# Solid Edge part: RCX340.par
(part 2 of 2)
sketch for "ExtrudedCutout_67" plane through (0, 0, 0) normal (0, 0, 1) x-axis (1, 0, 0)
  line (-7.15, 79.15) -> (-7.15, 26.85)
  line (-7.15, 26.85) -> (24.15, 26.85)
  line (24.15, 26.85) -> (24.15, 31.85)
  line (24.15, 31.85) -> (53.85, 31.85)
  line (53.85, 31.85) -> (53.85, 26.85)
  line (53.85, 26.85) -> (85.15, 26.85)
  line (85.15, 26.85) -> (85.15, 32.15)
  line (85.15, 32.15) -> (-6.85, 32.15)
  line (-6.85, 32.15) -> (-6.85, 78.85)
  line (-6.85, 78.85) -> (4.15, 78.85)
  line (4.15, 78.85) -> (4.15, 79.15)
  line (4.15, 79.15) -> (-7.15, 79.15)
extrude "ExtrudedCutout_67" cut finite 0.1 along -normal
sketch for "unnamed RevolvedProtrusion 3" plane through (-168, 0, 0) normal (1, 0, 0) x-axis (0, 1, 0)
  line (14.5, -6.5) -> (10.5, -6.5)
  line (10.5, -6.5) -> (10.5, -6)
  line (10.5, -6) -> (11, -6)
  line (11, -6) -> (11, -3.9)
  arc centre (12.5, -3.9) radius 1.5 from (11, -3.9) to (12.5, -2.4) cw
  line (12.5, -2.4) -> (14.5, -2.4)
  line (14.5, -2.4) -> (14.5, -6.5)
revolve "unnamed RevolvedProtrusion 3" add finite 360 deg about sketch line (14.5, -2.4) -> (14.5, -6.5)
sketch for "ExtrudedCutout_68" plane through (0, 0, 0) normal (0, 0, 1) x-axis (1, 0, 0)
  line (-170.1, 14.9) -> (-170.1, 14.1)
  line (-170.1, 14.1) -> (-168.9, 14.1)
  arc centre (-168.9, 13.6) radius 0.5 from (-168.9, 14.1) to (-168.4, 13.6) cw
  line (-168.4, 13.6) -> (-168.4, 12.4)
  line (-168.4, 12.4) -> (-167.6, 12.4)
  line (-167.6, 12.4) -> (-167.6, 13.6)
  arc centre (-167.1, 13.6) radius 0.5 from (-167.6, 13.6) to (-167.1, 14.1) cw
  line (-167.1, 14.1) -> (-165.9, 14.1)
  line (-165.9, 14.1) -> (-165.9, 14.9)
  line (-165.9, 14.9) -> (-167.1, 14.9)
  arc centre (-167.1, 15.4) radius 0.5 from (-167.1, 14.9) to (-167.6, 15.4) cw
  line (-167.6, 15.4) -> (-167.6, 16.6)
  line (-167.6, 16.6) -> (-168.4, 16.6)
  line (-168.4, 16.6) -> (-168.4, 15.4)
  arc centre (-168.9, 15.4) radius 0.5 from (-168.4, 15.4) to (-168.9, 14.9) cw
  line (-168.9, 14.9) -> (-170.1, 14.9)
extrude "ExtrudedCutout_68" cut finite 3.777 along -normal
sketch for "ExtrudedProtrusion_51" #1 plane through (0, 0, -15) normal (0, 0, 1) x-axis (1, 0, 0)
  line (-165.9, 70.83) -> (-165.9, 39.77)
  line (-165.9, 39.77) -> (-157.5, 39.77)
  line (-157.5, 39.77) -> (-157.5, 70.83)
  line (-157.5, 70.83) -> (-165.9, 70.83)
sketch for "ExtrudedProtrusion_51" #2 plane through (0, 0, -15) normal (0, 0, 1) x-axis (1, 0, 0)
  line (-164.2, 69.83) -> (-164.2, 40.67)
  line (-164.2, 40.67) -> (-161.8, 40.67)
  line (-161.8, 40.67) -> (-161.8, 41.47)
  line (-161.8, 41.47) -> (-160.8, 41.47)
  line (-160.8, 41.47) -> (-160.8, 40.67)
  line (-160.8, 40.67) -> (-159.1, 40.67)
  line (-159.1, 40.67) -> (-159.1, 41.47)
  line (-159.1, 41.47) -> (-158.7, 41.47)
  line (-158.7, 41.47) -> (-158.7, 42.2733)
  arc centre (-161.3, 43.77) radius 3 from (-158.7, 42.2733) to (-158.7, 45.2667) ccw
  line (-158.7, 45.2667) -> (-158.7, 45.97)
  line (-158.7, 45.97) -> (-159.1, 45.97)
  line (-159.1, 45.97) -> (-159.1, 46.57)
  line (-159.1, 46.57) -> (-158.7, 46.57)
  line (-158.7, 46.57) -> (-158.7, 49.8933)
  arc centre (-161.3, 51.39) radius 3 from (-158.7, 49.8933) to (-158.7, 52.8867) ccw
  line (-158.7, 52.8867) -> (-158.7, 53.59)
  line (-158.7, 53.59) -> (-159.1, 53.59)
  line (-159.1, 53.59) -> (-159.1, 54.19)
  line (-159.1, 54.19) -> (-158.7, 54.19)
  line (-158.7, 54.19) -> (-158.7, 57.5133)
  arc centre (-161.3, 59.01) radius 3 from (-158.7, 57.5133) to (-158.7, 60.5067) ccw
  line (-158.7, 60.5067) -> (-158.7, 61.21)
  line (-158.7, 61.21) -> (-159.1, 61.21)
  line (-159.1, 61.21) -> (-159.1, 61.81)
  line (-159.1, 61.81) -> (-158.7, 61.81)
  line (-158.7, 61.81) -> (-158.7, 65.1333)
  arc centre (-161.3, 66.63) radius 3 from (-158.7, 65.1333) to (-158.7, 68.1267) ccw
  line (-158.7, 68.1267) -> (-158.7, 68.83)
  line (-158.7, 68.83) -> (-159.1, 68.83)
  line (-159.1, 68.83) -> (-159.1, 69.83)
  line (-159.1, 69.83) -> (-164.2, 69.83)
extrude "ExtrudedProtrusion_51" add finite 15 along +normal
sketch for "ExtrudedProtrusion_52" plane through (0, 0, -15) normal (0, 0, 1) x-axis (1, 0, 0)
  line (-161.8, 67.33) -> (-161.8, 66.33)
  line (-161.8, 66.33) -> (-160.8, 66.33)
  line (-160.8, 66.33) -> (-160.8, 67.33)
  line (-160.8, 67.33) -> (-161.8, 67.33)
extrude "ExtrudedProtrusion_52" add finite 10 along +normal
pattern "unnamed Pattern 10" of "ExtrudedProtrusion_52"
extrude "unnamed Protrusion 16" add finite 10
extrude "unnamed Protrusion 17" add finite 10
extrude "unnamed Protrusion 18" add finite 10
sketch for "ExtrudedCutout_69" #1 plane through (0, 0, 0) normal (0, 0, 1) x-axis (1, 0, 0)
  circle centre (114.4, 116.5) radius 2.5
sketch for "ExtrudedCutout_69" #2 plane through (0, 0, 0) normal (0, 0, 1) x-axis (1, 0, 0)
  circle centre (114.4, 116.5) radius 1.75
extrude "ExtrudedCutout_69" cut finite 5 along -normal
"ExtrudedProtrusion_56" has 41 sketches; the first 24 follow
sketch for "ExtrudedProtrusion_56" #1 plane through (-177.5, 0, 0) normal (1, 0, 0) x-axis (0, 1, 0)
  arc centre (107.75, -43.75) radius 3 from (107.75, -40.75) to (104.75, -43.75) ccw
  line (104.75, -43.75) -> (104.75, -123.25)
  arc centre (107.75, -123.25) radius 3 from (104.75, -123.25) to (107.75, -126.25) ccw
  line (107.75, -126.25) -> (187.25, -126.25)
  arc centre (187.25, -123.25) radius 3 from (187.25, -126.25) to (190.25, -123.25) ccw
  line (190.25, -123.25) -> (190.25, -43.75)
  arc centre (187.25, -43.75) radius 3 from (190.25, -43.75) to (187.25, -40.75) ccw
  line (187.25, -40.75) -> (107.75, -40.75)
sketch for "ExtrudedProtrusion_56" #2 plane through (-177.5, 0, 0) normal (1, 0, 0) x-axis (0, 1, 0)
  circle centre (183.25, -119.25) radius 5
sketch for "ExtrudedProtrusion_56" #3 plane through (-177.5, 0, 0) normal (1, 0, 0) x-axis (0, 1, 0)
  circle centre (111.75, -119.25) radius 5
sketch for "ExtrudedProtrusion_56" #4 plane through (-177.5, 0, 0) normal (1, 0, 0) x-axis (0, 1, 0)
  line (121.1695, -111.2447) -> (116.9256, -115.4886)
  arc centre (147.5, -83.5) radius 44.25 from (116.9256, -115.4886) to (123.2294, -120.5) ccw
  line (123.2294, -120.5) -> (131.8615, -120.5)
  arc centre (131.8615, -119.5) radius 1 from (131.8615, -120.5) to (132.2599, -118.5828) ccw
  arc centre (147.5, -83.5) radius 38.25 from (132.2599, -118.5828) to (121.1695, -111.2447) cw
sketch for "ExtrudedProtrusion_56" #5 plane through (-177.5, 0, 0) normal (1, 0, 0) x-axis (0, 1, 0)
  arc centre (147.5, -83.5) radius 38.25 from (173.8305, -111.2447) to (162.7401, -118.5828) cw
  arc centre (163.1385, -119.5) radius 1 from (162.7401, -118.5828) to (163.1385, -120.5) ccw
  line (163.1385, -120.5) -> (171.7706, -120.5)
  arc centre (147.5, -83.5) radius 44.25 from (171.7706, -120.5) to (178.0744, -115.4886) ccw
  line (178.0744, -115.4886) -> (173.8305, -111.2447)
sketch for "ExtrudedProtrusion_56" #6 plane through (-177.5, 0, 0) normal (1, 0, 0) x-axis (0, 1, 0)
  line (126.8288, -105.5854) -> (122.5842, -109.83)
  arc centre (147.5, -83.5) radius 36.25 from (122.5842, -109.83) to (146.5, -119.7362) ccw
  line (146.5, -119.7362) -> (146.5, -113.7335)
  arc centre (147.5, -83.5) radius 30.25 from (146.5, -113.7335) to (126.8288, -105.5854) cw
sketch for "ExtrudedProtrusion_56" #7 plane through (-177.5, 0, 0) normal (1, 0, 0) x-axis (0, 1, 0)
  arc centre (147.5, -83.5) radius 30.25 from (168.1712, -105.5854) to (148.5, -113.7335) cw
  line (148.5, -113.7335) -> (148.5, -119.7362)
  arc centre (147.5, -83.5) radius 36.25 from (148.5, -119.7362) to (172.4158, -109.83) ccw
  line (172.4158, -109.83) -> (168.1712, -105.5854)
sketch for "ExtrudedProtrusion_56" #8 plane through (-177.5, 0, 0) normal (1, 0, 0) x-axis (0, 1, 0)
  line (108.75, -105) -> (106.5, -105)
  line (106.5, -105) -> (106.5, -110)
  line (106.5, -110) -> (108.75, -110)
  line (108.75, -110) -> (108.75, -105)
sketch for "ExtrudedProtrusion_56" #9 plane through (-177.5, 0, 0) normal (1, 0, 0) x-axis (0, 1, 0)
  line (186.25, -105) -> (186.25, -110)
  line (186.25, -110) -> (188.5, -110)
  line (188.5, -110) -> (188.5, -105)
  line (188.5, -105) -> (186.25, -105)
sketch for "ExtrudedProtrusion_56" #10 plane through (-177.5, 0, 0) normal (1, 0, 0) x-axis (0, 1, 0)
  line (132.4899, -99.9243) -> (128.2439, -104.1704)
  arc centre (147.5, -83.5) radius 28.25 from (128.2439, -104.1704) to (146.5, -111.7323) ccw
  line (146.5, -111.7323) -> (146.5, -105.7275)
  arc centre (147.5, -83.5) radius 22.25 from (146.5, -105.7275) to (132.4899, -99.9243) cw
sketch for "ExtrudedProtrusion_56" #11 plane through (-177.5, 0, 0) normal (1, 0, 0) x-axis (0, 1, 0)
  arc centre (147.5, -83.5) radius 22.25 from (162.5101, -99.9243) to (148.5, -105.7275) cw
  line (148.5, -105.7275) -> (148.5, -111.7323)
  arc centre (147.5, -83.5) radius 28.25 from (148.5, -111.7323) to (166.7561, -104.1704) ccw
  line (166.7561, -104.1704) -> (162.5101, -99.9243)
sketch for "ExtrudedProtrusion_56" #12 plane through (-177.5, 0, 0) normal (1, 0, 0) x-axis (0, 1, 0)
  arc centre (111.5, -99.1385) radius 1 from (112.4172, -98.7401) to (110.5, -99.1385) ccw
  line (110.5, -99.1385) -> (110.5, -107.7706)
  arc centre (147.5, -83.5) radius 44.25 from (110.5, -107.7706) to (115.5114, -114.0744) ccw
  line (115.5114, -114.0744) -> (119.7553, -109.8305)
  arc centre (147.5, -83.5) radius 38.25 from (119.7553, -109.8305) to (112.4172, -98.7401) cw
sketch for "ExtrudedProtrusion_56" #13 plane through (-177.5, 0, 0) normal (1, 0, 0) x-axis (0, 1, 0)
  arc centre (183.5, -99.1385) radius 1 from (184.5, -99.1385) to (182.5828, -98.7401) ccw
  arc centre (147.5, -83.5) radius 38.25 from (182.5828, -98.7401) to (175.2447, -109.8305) cw
  line (175.2447, -109.8305) -> (179.4886, -114.0744)
  arc centre (147.5, -83.5) radius 44.25 from (179.4886, -114.0744) to (184.5, -107.7706) ccw
  line (184.5, -107.7706) -> (184.5, -99.1385)
sketch for "ExtrudedProtrusion_56" #14 plane through (-177.5, 0, 0) normal (1, 0, 0) x-axis (0, 1, 0)
  line (135.4988, -96.9154) -> (133.9057, -98.5085)
  arc centre (147.5, -83.5) radius 20.25 from (133.9057, -98.5085) to (146.5, -103.7253) ccw
  line (146.5, -103.7253) -> (146.5, -101.4722)
  arc centre (147.5, -83.5) radius 18 from (146.5, -101.4722) to (135.4988, -96.9154) cw
sketch for "ExtrudedProtrusion_56" #15 plane through (-177.5, 0, 0) normal (1, 0, 0) x-axis (0, 1, 0)
  arc centre (147.5, -83.5) radius 18 from (159.5012, -96.9154) to (148.5, -101.4722) cw
  line (148.5, -101.4722) -> (148.5, -103.7253)
  arc centre (147.5, -83.5) radius 20.25 from (148.5, -103.7253) to (161.0943, -98.5085) ccw
  line (161.0943, -98.5085) -> (159.5012, -96.9154)
sketch for "ExtrudedProtrusion_56" #16 plane through (-177.5, 0, 0) normal (1, 0, 0) x-axis (0, 1, 0)
  line (117.2665, -84.5) -> (111.2638, -84.5)
  arc centre (147.5, -83.5) radius 36.25 from (111.2638, -84.5) to (121.17, -108.4158) ccw
  line (121.17, -108.4158) -> (125.4146, -104.1712)
  arc centre (147.5, -83.5) radius 30.25 from (125.4146, -104.1712) to (117.2665, -84.5) cw
sketch for "ExtrudedProtrusion_56" #17 plane through (-177.5, 0, 0) normal (1, 0, 0) x-axis (0, 1, 0)
  arc centre (147.5, -83.5) radius 20.25 from (127.2747, -84.5) to (132.4915, -97.0943) ccw
  line (132.4915, -97.0943) -> (134.0846, -95.5012)
  arc centre (147.5, -83.5) radius 18 from (134.0846, -95.5012) to (129.5278, -84.5) cw
  line (129.5278, -84.5) -> (127.2747, -84.5)
sketch for "ExtrudedProtrusion_56" #18 plane through (-177.5, 0, 0) normal (1, 0, 0) x-axis (0, 1, 0)
  arc centre (147.5, -83.5) radius 28.25 from (119.2677, -84.5) to (126.8296, -102.7561) ccw
  line (126.8296, -102.7561) -> (131.0757, -98.5101)
  arc centre (147.5, -83.5) radius 22.25 from (131.0757, -98.5101) to (125.2725, -84.5) cw
  line (125.2725, -84.5) -> (119.2677, -84.5)
sketch for "ExtrudedProtrusion_56" #19 plane through (-177.5, 0, 0) normal (1, 0, 0) x-axis (0, 1, 0)
  arc centre (147.5, -83.5) radius 30.25 from (177.7335, -84.5) to (169.5854, -104.1712) cw
  line (169.5854, -104.1712) -> (173.83, -108.4158)
  arc centre (147.5, -83.5) radius 36.25 from (173.83, -108.4158) to (183.7362, -84.5) ccw
  line (183.7362, -84.5) -> (177.7335, -84.5)
sketch for "ExtrudedProtrusion_56" #20 plane through (-177.5, 0, 0) normal (1, 0, 0) x-axis (0, 1, 0)
  line (167.7253, -84.5) -> (165.4722, -84.5)
  arc centre (147.5, -83.5) radius 18 from (165.4722, -84.5) to (160.9154, -95.5012) cw
  line (160.9154, -95.5012) -> (162.5085, -97.0943)
  arc centre (147.5, -83.5) radius 20.25 from (162.5085, -97.0943) to (167.7253, -84.5) ccw
sketch for "ExtrudedProtrusion_56" #21 plane through (-177.5, 0, 0) normal (1, 0, 0) x-axis (0, 1, 0)
  line (175.7323, -84.5) -> (169.7275, -84.5)
  arc centre (147.5, -83.5) radius 22.25 from (169.7275, -84.5) to (163.9243, -98.5101) cw
  line (163.9243, -98.5101) -> (168.1704, -102.7561)
  arc centre (147.5, -83.5) radius 28.25 from (168.1704, -102.7561) to (175.7323, -84.5) ccw
sketch for "ExtrudedProtrusion_56" #22 plane through (-177.5, 0, 0) normal (1, 0, 0) x-axis (0, 1, 0)
  arc centre (147.5, -83.5) radius 20.25 from (132.4915, -69.9057) to (127.2747, -82.5) ccw
  line (127.2747, -82.5) -> (129.5278, -82.5)
  arc centre (147.5, -83.5) radius 18 from (129.5278, -82.5) to (134.0846, -71.4988) cw
  line (134.0846, -71.4988) -> (132.4915, -69.9057)
sketch for "ExtrudedProtrusion_56" #23 plane through (-177.5, 0, 0) normal (1, 0, 0) x-axis (0, 1, 0)
  line (162.5085, -69.9057) -> (160.9154, -71.4988)
  arc centre (147.5, -83.5) radius 18 from (160.9154, -71.4988) to (165.4722, -82.5) cw
  line (165.4722, -82.5) -> (167.7253, -82.5)
  arc centre (147.5, -83.5) radius 20.25 from (167.7253, -82.5) to (162.5085, -69.9057) ccw
sketch for "ExtrudedProtrusion_56" #24 plane through (-177.5, 0, 0) normal (1, 0, 0) x-axis (0, 1, 0)
  arc centre (147.5, -83.5) radius 28.25 from (126.8296, -64.2439) to (119.2677, -82.5) ccw
  line (119.2677, -82.5) -> (125.2725, -82.5)
  arc centre (147.5, -83.5) radius 22.25 from (125.2725, -82.5) to (131.0757, -68.4899) cw
  line (131.0757, -68.4899) -> (126.8296, -64.2439)
extrude "ExtrudedProtrusion_56" add finite 10.5 along -normal
sketch for "ExtrudedProtrusion_57" plane through (-177.5, 0, 0) normal (1, 0, 0) x-axis (0, 1, 0)
  arc centre (107.75, -43.75) radius 3 from (107.75, -40.75) to (104.75, -43.75) ccw
  line (104.75, -43.75) -> (104.75, -123.25)
  arc centre (107.75, -123.25) radius 3 from (104.75, -123.25) to (107.75, -126.25) ccw
  line (107.75, -126.25) -> (187.25, -126.25)
  arc centre (187.25, -123.25) radius 3 from (187.25, -126.25) to (190.25, -123.25) ccw
  line (190.25, -123.25) -> (190.25, -43.75)
  arc centre (187.25, -43.75) radius 3 from (190.25, -43.75) to (187.25, -40.75) ccw
  line (187.25, -40.75) -> (107.75, -40.75)
extrude "ExtrudedProtrusion_57" add finite 4.777 along -normal
sketch for "ExtrudedProtrusion_58" #1 plane through (-177.5, 0, 0) normal (1, 0, 0) x-axis (0, 1, 0)
  circle centre (183.25, -119.25) radius 4
sketch for "ExtrudedProtrusion_58" #2 plane through (-177.5, 0, 0) normal (1, 0, 0) x-axis (0, 1, 0)
  line (183.65, -117.15) -> (182.85, -117.15)
  line (182.85, -117.15) -> (182.85, -118.35)
  arc centre (182.35, -118.35) radius 0.5 from (182.85, -118.35) to (182.35, -118.85) cw
  line (182.35, -118.85) -> (181.15, -118.85)
  line (181.15, -118.85) -> (181.15, -119.65)
  line (181.15, -119.65) -> (182.35, -119.65)
  arc centre (182.35, -120.15) radius 0.5 from (182.35, -119.65) to (182.85, -120.15) cw
  line (182.85, -120.15) -> (182.85, -121.35)
  line (182.85, -121.35) -> (183.65, -121.35)
  line (183.65, -121.35) -> (183.65, -120.15)
  arc centre (184.15, -120.15) radius 0.5 from (183.65, -120.15) to (184.15, -119.65) cw
  line (184.15, -119.65) -> (185.35, -119.65)
  line (185.35, -119.65) -> (185.35, -118.85)
  line (185.35, -118.85) -> (184.15, -118.85)
  arc centre (184.15, -118.35) radius 0.5 from (184.15, -118.85) to (183.65, -118.35) cw
  line (183.65, -118.35) -> (183.65, -117.15)
extrude "ExtrudedProtrusion_58" add finite 7 along -normal
pattern "unnamed Pattern 11" of "ExtrudedProtrusion_58"
extrude "unnamed Protrusion 19" add finite 7
extrude "unnamed Protrusion 20" add finite 7
extrude "unnamed Protrusion 21" add finite 7
sketch for "ExtrudedCutout_70" plane through (0, 0, 0) normal (0, -1, 0) x-axis (1, 0, 0)
  line (98, 23) -> (104.5, 23)
  line (104.5, 23) -> (104.5, 0)
  line (104.5, 0) -> (103.8, 0)
  arc centre (103.8, -2.3) radius 2.3 from (103.8, 0) to (101.5, -2.3) ccw
  line (101.5, -2.3) -> (101.5, -23)
  line (101.5, -23) -> (101, -23)
  line (101, -23) -> (101, -2.3)
  arc centre (98.7, -2.3) radius 2.3 from (101, -2.3) to (98.7, 0) ccw
  line (98.7, 0) -> (98, 0)
  line (98, 0) -> (98, 23)
extrude "ExtrudedCutout_70" cut finite 200 along -normal
sketch for "ExtrudedCutout_71" plane through (0, 0, 0) normal (0, -1, 0) x-axis (1, 0, 0)
  line (-180.5, -5) -> (-180.5, 5)
  line (-180.5, 5) -> (-172.5, 5)
  line (-172.5, 5) -> (-172.5, 0)
  line (-172.5, 0) -> (-175.2, 0)
  arc centre (-175.2, -2.3) radius 2.3 from (-175.2, 0) to (-177.5, -2.3) ccw
  line (-177.5, -2.3) -> (-177.5, -5)
  line (-177.5, -5) -> (-180.5, -5)
extrude "ExtrudedCutout_71" cut finite 200 along -normal
sketch for "ExtrudedCutout_72" plane through (0, 0, 0) normal (0, -1, 0) x-axis (1, 0, 0)
  line (-180.5, -11.5) -> (-180.5, -1.5)
  line (-180.5, -1.5) -> (-172.5, -1.5)
  line (-172.5, -1.5) -> (-172.5, -6.5)
  line (-172.5, -6.5) -> (-175.2, -6.5)
  arc centre (-175.2, -8.8) radius 2.3 from (-175.2, -6.5) to (-177.5, -8.8) ccw
  line (-177.5, -8.8) -> (-177.5, -11.5)
  line (-177.5, -11.5) -> (-180.5, -11.5)
extrude "ExtrudedCutout_72" cut finite 23.5 along -normal
sketch for "ExtrudedCutout_73" plane through (0, 0, 0) normal (0, -1, 0) x-axis (1, 0, 0)
  line (172.5, 5) -> (180.5, 5)
  line (180.5, 5) -> (180.5, -5)
  line (180.5, -5) -> (177.5, -5)
  line (177.5, -5) -> (177.5, -2.3)
  arc centre (175.2, -2.3) radius 2.3 from (177.5, -2.3) to (175.2, 0) ccw
  line (175.2, 0) -> (172.5, 0)
  line (172.5, 0) -> (172.5, 5)
extrude "ExtrudedCutout_73" cut finite 200 along -normal
sketch for "ExtrudedCutout_74" plane through (0, 0, 0) normal (0, -1, 0) x-axis (1, 0, 0)
  arc centre (142, -111) radius 1.5 from (142, -112.5) to (142, -109.5) cw
  line (142, -109.5) -> (159, -109.5)
  arc centre (159, -111) radius 1.5 from (159, -109.5) to (159, -112.5) cw
  line (159, -112.5) -> (142, -112.5)
extrude "ExtrudedCutout_74" cut finite 0.777 along -normal
pattern "unnamed Pattern 12" of "ExtrudedCutout_74"
extrude "unnamed Cutout 55" cut finite 0.777
extrude "unnamed Cutout 56" cut finite 0.777
extrude "unnamed Cutout 57" cut finite 0.777
extrude "unnamed Cutout 58" cut finite 0.777
extrude "unnamed Cutout 59" cut finite 0.777
extrude "unnamed Cutout 60" cut finite 0.777
extrude "unnamed Cutout 61" cut finite 0.777
extrude "unnamed Cutout 62" cut finite 0.777
extrude "unnamed Cutout 63" cut finite 0.777
extrude "unnamed Cutout 64" cut finite 0.777
sketch for "ExtrudedCutout_85" plane through (0, 0, 0) normal (0, 0, 1) x-axis (1, 0, 0)
  line (110.5, 183.5) -> (110.5, 181.5)
  line (110.5, 181.5) -> (122.5, 181.5)
  line (122.5, 181.5) -> (122.5, 183.5)
  line (122.5, 183.5) -> (110.5, 183.5)
extrude "ExtrudedCutout_85" cut finite 0.777 along -normal
sketch for "ExtrudedCutout_86" plane through (0, 0, 0) normal (0, 0, 1) x-axis (1, 0, 0)
  line (110.5, 179.5) -> (110.5, 177.5)
  line (110.5, 177.5) -> (122.5, 177.5)
  line (122.5, 177.5) -> (122.5, 179.5)
  line (122.5, 179.5) -> (110.5, 179.5)
extrude "ExtrudedCutout_86" cut finite 0.777 along -normal
sketch for "Hole_4" plane through (112.1, 162.5, 0) normal (0, 0, -1) x-axis (1, 0, 0)
  hole centre (0, 0) bore radius 1.1
hole "Hole_4" diameter 2.2 finite
sketch for "unnamed RevolvedProtrusion 4" plane through (171.5, 0, 0) normal (1, 0, 0) x-axis (0, 1, 0)
  line (195, -26) -> (195, -23.0761)
  arc centre (195.2, -23.0761) radius 0.2 from (195, -23.0761) to (195.2244, -22.8775) cw
  line (195.2244, -22.8775) -> (196.0085, -22.9738)
  arc centre (195.9476, -23.4701) radius 0.5 from (196.0085, -22.9738) to (196.4166, -23.2968) cw
  arc centre (189.1, -26) radius 7.8 from (196.4166, -23.2968) to (196.9, -26) cw
  line (196.9, -26) -> (195, -26)
revolve "unnamed RevolvedProtrusion 4" add finite 360 deg about sketch line (196.9, -26) -> (195, -26)
pattern "unnamed Pattern 13" of "unnamed RevolvedProtrusion 4"
revolve "unnamed RevolvedProtrusion 5" add finite 360 deg
revolve "unnamed RevolvedProtrusion 6" add finite 360 deg
sketch for "unnamed RevolvedProtrusion 7" plane through (167.5, 0, 0) normal (1, 0, 0) x-axis (0, 1, 0)
  line (195, -124) -> (195, -121.0761)
  arc centre (195.2, -121.0761) radius 0.2 from (195, -121.0761) to (195.2244, -120.8775) cw
  line (195.2244, -120.8775) -> (196.0085, -120.9738)
  arc centre (195.9476, -121.4701) radius 0.5 from (196.0085, -120.9738) to (196.4166, -121.2968) cw
  arc centre (189.1, -124) radius 7.8 from (196.4166, -121.2968) to (196.9, -124) cw
  line (196.9, -124) -> (195, -124)
revolve "unnamed RevolvedProtrusion 7" add finite 360 deg about sketch line (196.9, -124) -> (195, -124)
sketch for "unnamed RevolvedProtrusion 8" plane through (107.5, 0, 0) normal (1, 0, 0) x-axis (0, 1, 0)
  line (195, -114.5) -> (195, -111.5761)
  arc centre (195.2, -111.5761) radius 0.2 from (195, -111.5761) to (195.2244, -111.3775) cw
  line (195.2244, -111.3775) -> (196.0085, -111.4738)
  arc centre (195.9476, -111.9701) radius 0.5 from (196.0085, -111.4738) to (196.4166, -111.7968) cw
  arc centre (189.1, -114.5) radius 7.8 from (196.4166, -111.7968) to (196.9, -114.5) cw
  line (196.9, -114.5) -> (195, -114.5)
revolve "unnamed RevolvedProtrusion 8" add finite 360 deg about sketch line (196.9, -114.5) -> (195, -114.5)
sketch for "unnamed RevolvedProtrusion 9" plane through (57.5, 0, 0) normal (1, 0, 0) x-axis (0, 1, 0)
  line (195, -76) -> (195, -73.0761)
  arc centre (195.2, -73.0761) radius 0.2 from (195, -73.0761) to (195.2244, -72.8775) cw
  line (195.2244, -72.8775) -> (196.0085, -72.9738)
  arc centre (195.9476, -73.4701) radius 0.5 from (196.0085, -72.9738) to (196.4166, -73.2968) cw
  arc centre (189.1, -76) radius 7.8 from (196.4166, -73.2968) to (196.9, -76) cw
  line (196.9, -76) -> (195, -76)
revolve "unnamed RevolvedProtrusion 9" add finite 360 deg about sketch line (196.9, -76) -> (195, -76)
sketch for "unnamed RevolvedProtrusion 10" plane through (-122.5, 0, 0) normal (1, 0, 0) x-axis (0, 1, 0)
  line (195, -76) -> (195, -73.0761)
  arc centre (195.2, -73.0761) radius 0.2 from (195, -73.0761) to (195.2244, -72.8775) cw
  line (195.2244, -72.8775) -> (196.0085, -72.9738)
  arc centre (195.9476, -73.4701) radius 0.5 from (196.0085, -72.9738) to (196.4166, -73.2968) cw
  arc centre (189.1, -76) radius 7.8 from (196.4166, -73.2968) to (196.9, -76) cw
  line (196.9, -76) -> (195, -76)
revolve "unnamed RevolvedProtrusion 10" add finite 360 deg about sketch line (196.9, -76) -> (195, -76)
sketch for "unnamed RevolvedProtrusion 11" plane through (-171.5, 0, 0) normal (1, 0, 0) x-axis (0, 1, 0)
  line (195, -26) -> (195, -23.0761)
  arc centre (195.2, -23.0761) radius 0.2 from (195, -23.0761) to (195.2244, -22.8775) cw
  line (195.2244, -22.8775) -> (196.0085, -22.9738)
  arc centre (195.9476, -23.4701) radius 0.5 from (196.0085, -22.9738) to (196.4166, -23.2968) cw
  arc centre (189.1, -26) radius 7.8 from (196.4166, -23.2968) to (196.9, -26) cw
  line (196.9, -26) -> (195, -26)
revolve "unnamed RevolvedProtrusion 11" add finite 360 deg about sketch line (196.9, -26) -> (195, -26)
sketch for "unnamed RevolvedProtrusion 12" plane through (-167.5, 0, 0) normal (1, 0, 0) x-axis (0, 1, 0)
  line (195, -124) -> (195, -121.0761)
  arc centre (195.2, -121.0761) radius 0.2 from (195, -121.0761) to (195.2244, -120.8775) cw
  line (195.2244, -120.8775) -> (196.0085, -120.9738)
  arc centre (195.9476, -121.4701) radius 0.5 from (196.0085, -120.9738) to (196.4166, -121.2968) cw
  arc centre (189.1, -124) radius 7.8 from (196.4166, -121.2968) to (196.9, -124) cw
  line (196.9, -124) -> (195, -124)
revolve "unnamed RevolvedProtrusion 12" add finite 360 deg about sketch line (196.9, -124) -> (195, -124)
sketch for "unnamed RevolvedProtrusion 13" plane through (160.4, 0, 0) normal (1, 0, 0) x-axis (0, 1, 0)
  line (13.5, 2.19) -> (14.45, 2.19)
  arc centre (14.45, 1.39) radius 0.8 from (14.45, 2.19) to (15.25, 1.39) cw
  line (15.25, 1.39) -> (15.25, 0.9)
  line (15.25, 0.9) -> (15.5, 0.9)
  line (15.5, 0.9) -> (15.5, 0.4)
  line (15.5, 0.4) -> (15.65, 0.4)
  line (15.65, 0.4) -> (15.65, 0)
  line (15.65, 0) -> (13.5, 0)
  line (13.5, 0) -> (13.5, 2.19)
revolve "unnamed RevolvedProtrusion 13" add finite 360 deg about sketch line (13.5, 0) -> (13.5, 2.19)
pattern "unnamed Pattern 14" of "unnamed RevolvedProtrusion 13"
revolve "unnamed RevolvedProtrusion 14" add finite 360 deg
revolve "unnamed RevolvedProtrusion 15" add finite 360 deg
revolve "unnamed RevolvedProtrusion 16" add finite 360 deg
sketch for "unnamed RevolvedProtrusion 17" plane through (160.4, 0, 0) normal (1, 0, 0) x-axis (0, 1, 0)
  line (104.5, 2.19) -> (105.45, 2.19)
  arc centre (105.45, 1.39) radius 0.8 from (105.45, 2.19) to (106.25, 1.39) cw
  line (106.25, 1.39) -> (106.25, 0.9)
  line (106.25, 0.9) -> (106.5, 0.9)
  line (106.5, 0.9) -> (106.5, 0.4)
  line (106.5, 0.4) -> (106.65, 0.4)
  line (106.65, 0.4) -> (106.65, 0)
  line (106.65, 0) -> (104.5, 0)
  line (104.5, 0) -> (104.5, 2.19)
revolve "unnamed RevolvedProtrusion 17" add finite 360 deg about sketch line (104.5, 0) -> (104.5, 2.19)
pattern "unnamed Pattern 15" of "unnamed RevolvedProtrusion 17"
revolve "unnamed RevolvedProtrusion 18" add finite 360 deg
revolve "unnamed RevolvedProtrusion 19" add finite 360 deg
revolve "unnamed RevolvedProtrusion 20" add finite 360 deg
sketch for "unnamed RevolvedProtrusion 21" plane through (107.5, 0, 0) normal (1, 0, 0) x-axis (0, 1, 0)
  line (195, -8) -> (195, -5.0761)
  arc centre (195.2, -5.0761) radius 0.2 from (195, -5.0761) to (195.2244, -4.8775) cw
  line (195.2244, -4.8775) -> (196.0085, -4.9738)
  arc centre (195.9476, -5.4701) radius 0.5 from (196.0085, -4.9738) to (196.4166, -5.2968) cw
  arc centre (189.1, -8) radius 7.8 from (196.4166, -5.2968) to (196.9, -8) cw
  line (196.9, -8) -> (195, -8)
revolve "unnamed RevolvedProtrusion 21" add finite 360 deg about sketch line (196.9, -8) -> (195, -8)
sketch for "unnamed RevolvedProtrusion 22" plane through (171.5, 0, 0) normal (1, 0, 0) x-axis (0, 1, 0)
  arc centre (5.9, -26) radius 7.8 from (-1.9, -26) to (-1.4166, -23.2968) cw
  arc centre (-0.9476, -23.4701) radius 0.5 from (-1.4166, -23.2968) to (-1.0085, -22.9738) cw
  line (-1.0085, -22.9738) -> (-0.2244, -22.8775)
  arc centre (-0.2, -23.0761) radius 0.2 from (-0.2244, -22.8775) to (0, -23.0761) cw
  line (0, -23.0761) -> (0, -26)
  line (0, -26) -> (-1.9, -26)
revolve "unnamed RevolvedProtrusion 22" add finite 360 deg about sketch line (0, -26) -> (-1.9, -26)
pattern "unnamed Pattern 16" of "unnamed RevolvedProtrusion 22"
revolve "unnamed RevolvedProtrusion 23" add finite 360 deg
revolve "unnamed RevolvedProtrusion 24" add finite 360 deg
sketch for "unnamed RevolvedProtrusion 25" plane through (0, 0, -124) normal (0, 0, 1) x-axis (1, 0, 0)
  arc centre (167.5, 5.9) radius 7.8 from (167.5, -1.9) to (164.7968, -1.4166) cw
  arc centre (164.9701, -0.9476) radius 0.5 from (164.7968, -1.4166) to (164.4738, -1.0085) cw
  line (164.4738, -1.0085) -> (164.3775, -0.2244)
  arc centre (164.5761, -0.2) radius 0.2 from (164.3775, -0.2244) to (164.5761, 0) cw
  line (164.5761, 0) -> (167.5, 0)
  line (167.5, 0) -> (167.5, -1.9)
revolve "unnamed RevolvedProtrusion 25" add finite 360 deg about sketch line (167.5, 0) -> (167.5, -1.9)
sketch for "unnamed RevolvedProtrusion 26" plane through (0, 0, -124) normal (0, 0, 1) x-axis (1, 0, 0)
  arc centre (112.5, 5.9) radius 7.8 from (112.5, -1.9) to (109.7968, -1.4166) cw
  arc centre (109.9701, -0.9476) radius 0.5 from (109.7968, -1.4166) to (109.4738, -1.0085) cw
  line (109.4738, -1.0085) -> (109.3775, -0.2244)
  arc centre (109.5761, -0.2) radius 0.2 from (109.3775, -0.2244) to (109.5761, 0) cw
  line (109.5761, 0) -> (112.5, 0)
  line (112.5, 0) -> (112.5, -1.9)
revolve "unnamed RevolvedProtrusion 26" add finite 360 deg about sketch line (112.5, 0) -> (112.5, -1.9)
sketch for "unnamed RevolvedProtrusion 27" plane through (0, 0, -114.5) normal (0, 0, 1) x-axis (1, 0, 0)
  arc centre (107.5, 5.9) radius 7.8 from (107.5, -1.9) to (104.7968, -1.4166) cw
  arc centre (104.9701, -0.9476) radius 0.5 from (104.7968, -1.4166) to (104.4738, -1.0085) cw
  line (104.4738, -1.0085) -> (104.3775, -0.2244)
  arc centre (104.5761, -0.2) radius 0.2 from (104.3775, -0.2244) to (104.5761, 0) cw
  line (104.5761, 0) -> (107.5, 0)
  line (107.5, 0) -> (107.5, -1.9)
revolve "unnamed RevolvedProtrusion 27" add finite 360 deg about sketch line (107.5, 0) -> (107.5, -1.9)
Other named dimensions: "CoordinateSystem_2": Z_Rotation = 180 deg; X_Translation = 155 mm; Y_Translation = 204 mm; Z_Translation = -130 mm | "CoordinateSystem_3": Z_Rotation = 180 deg; X_Translation = 155 mm; Y_Translation = 204 mm; Z_Translation = -130 mm | "CoordinateSystem_4": X_Rotation = 90 deg; X_Translation = 37.5 mm; Y_Translation = 195 mm; Z_Translation = -111 mm | "CoordinateSystem_5": X_Rotation = 90 deg; X_Translation = 119 mm; Y_Translation = 195 mm; Z_Translation = -111 mm | "CoordinateSystem_6": Y_Rotation = 90 deg; X_Translation = -180 mm | "CoordinateSystem_7": X_Translation = -129 mm; Y_Translation = 9.5 mm; Z_Translation = -6.5 mm | "CoordinateSystem_8": X_Translation = -128.12 mm; Y_Translation = 10.32 mm; Z_Translation = -21.5 mm | "CoordinateSystem_9": X_Translation = -121.97 mm; Y_Translation = 14.7 mm; Z_Translation = -21.5 mm | "CoordinateSystem_10": X_Translation = -60.97 mm; Y_Translation = 14.7 mm; Z_Translation = -21.5 mm | "CoordinateSystem_11": X_Translation = 0.03 mm; Y_Translation = 14.7 mm; Z_Translation = -21.5 mm | "CoordinateSystem_12": X_Translation = 61.03 mm; Y_Translation = 14.7 mm; Z_Translation = -21.5 mm | "CoordinateSystem_13": Z_Rotation = -90 deg; X_Translation = -161.8 mm; Y_Translation = 66.33 mm; Z_Translation = -15 mm | "CoordinateSystem_14": X_Rotation = -180 deg; Y_Rotation = -90 deg; X_Translation = -177.5 mm; Y_Translation = 183.25 mm; Z_Translation = -119.25 mm | "CoordinateSystem_15": X_Rotation = -90 deg; Y_Rotation = -90 deg; X_Translation = 159 mm; Z_Translation = -111 mm | "CoordinateSystem_16": X_Rotation = -180 deg; X_Translation = 112.1 mm; Y_Translation = 162.5 mm | "CoordinateSystem_17": X_Rotation = -90 deg; Y_Rotation = 90 deg; X_Translation = 171.5 mm; Y_Translation = 195 mm; Z_Translation = -26 mm | "CoordinateSystem_18": Z_Rotation = 90 deg; X_Translation = 160.4 mm; Y_Translation = 13.5 mm | "CoordinateSystem_19": Z_Rotation = 90 deg; X_Translation = 160.4 mm; Y_Translation = 104.5 mm | "CoordinateSystem_20": X_Rotation = -90 deg; Y_Rotation = 90 deg; X_Translation = 171.5 mm; Z_Translation = -26 mm
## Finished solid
Body 1: solid body, 1809 faces, 4403 edges, 2799 vertices.
  Faces by surface: plane 1296, cylinder 438, torus 41, cone 18, sphere 16
  Edges by curve: line 3446, circle 936, intersection 12, ellipse 9
Bounding box of the edges (mm; curved faces can reach further): 367.500 x 225.000 x 132.190, from (-188, -15, -130) to (179.5, 210, 2.19).
Cylindrical faces by radius (mm): R0.0777 x2, R0.1 x24, R0.2 x24, R0.25 x2, R0.5 x29, R1 x64, R1.1 x1, R1.3 x8, R1.41 x2, R1.45 x2, R1.5 x140, R1.75 x9, R1.8 x2, R2 x12, R2.15 x8, R2.3 x12, R2.5 x6, R2.75 x6, R3 x8, R3.5 x2, R4 x6, R4.1 x1, R5 x4, R18 x8, R20.25 x8, R22.25 x8, R28.25 x8, R30.25 x8, R36.25 x8, R38.25 x8, R44.25 x8
Conical faces (half-angle, radius in mm at the cone's reference point): 7 deg R3.0262 x6, 7 deg R3.1225 x10, 45 deg R3.7 x1, 45 deg R4 x1
Toroidal faces (ring radius, tube radius in mm): R0.95 r0.8 x8, R2 r1.5 x1, R2.5299 r0.5 x16, R2.9239 r0.2 x16
Spherical faces by radius (mm): R7.8 x16
Planar faces by outward normal: +x 162, +y 244, +z 248, -x 222, -y 201, -z 93, oblique 126
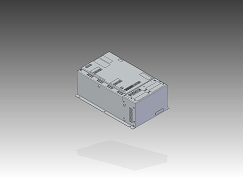
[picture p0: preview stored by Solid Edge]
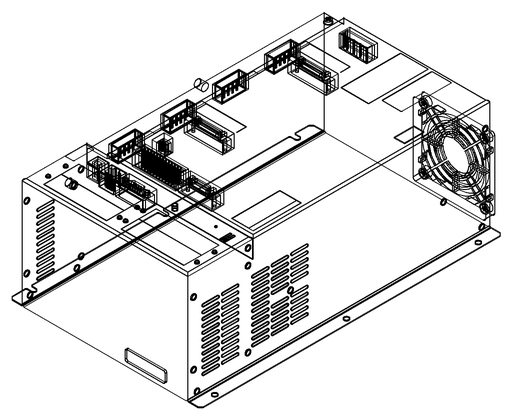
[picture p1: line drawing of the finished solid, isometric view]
